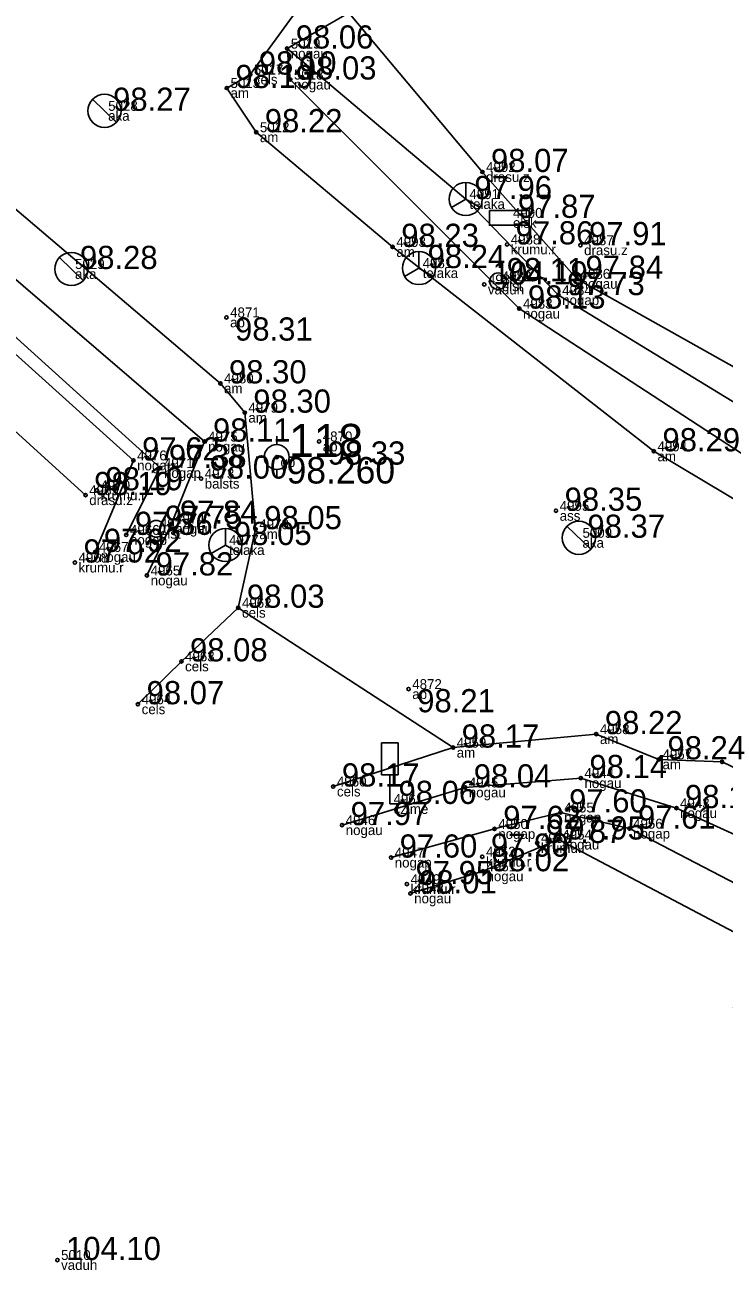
# Model space of a CAD drawing. Extents: x 614911 to 615803, y 262110 to 264311.
# Drawn here: x 615316.57 to 615337.66, y 264059.95 to 264097.55 of the extents above; entities that cross this region are included whole.
import ezdxf

# ---------------------------------------------------------------- set-up
doc = ezdxf.new("R2010")
doc.units = 0
for name, color, linetype in [('Level 12', 7, 'Continuous'), ('Level 16', 7, 'Continuous'), ('Level 18', 7, 'Continuous'), ('Level 19', 7, 'Continuous'), ('Level 31', 7, 'Continuous'), ('Level 35', 7, 'Continuous'), ('Level 37', 7, 'Continuous'), ('Level 49', 7, 'Continuous'), ('Level 53', 7, 'Continuous'), ('Level 54', 7, 'Continuous'), ('Level 57', 7, 'Continuous'), ('Level 58', 7, 'Continuous')]:
    doc.layers.add(name, color=color, linetype=linetype)

msp = doc.modelspace()

# ---------------------------------------------------------------- linework, layer by layer
at = {"layer": 'Level 12'}
for p, q in [((615318.611, 264095.3), (615319.329, 264094.604)), ((615317.612, 264090.524), (615318.33, 264089.828)), ((615332.921, 264082.409), (615333.639, 264081.713))]:
    msp.add_line(p, q, dxfattribs=at)
for centre in [(615318.97, 264094.952), (615317.971, 264090.176), (615333.28, 264082.061)]:
    msp.add_circle(centre, 0.5, dxfattribs=at)
at = {"layer": 'Level 16'}
for p, q in [((615327.826, 264075.872), (615327.326, 264075.872)), ((615327.326, 264074.903), (615327.326, 264075.872)), ((615327.826, 264074.903), (615327.826, 264075.872)), ((615327.826, 264074.903), (615327.326, 264074.903)), ((615327.58, 264074.903), (615327.58, 264074.025)), ((615327.58, 264074.025), (615327.895, 264074.025))]:
    msp.add_line(p, q, dxfattribs=at)
at = {"layer": 'Level 18'}
msp.add_lwpolyline([(615330.582, 264091.945), (615331.782, 264091.945), (615331.782, 264091.495), (615330.582, 264091.495)], close=True, dxfattribs=at)
for centre in [(615330.844, 264089.808), (615320.531, 264082.335)]:
    msp.add_circle(centre, 0.25, dxfattribs=at)
at = {"layer": 'Level 19'}
for p, q in [((615324.168, 264084.875), (615324.168, 264085.125)), ((615323.543, 264084.5), (615323.793, 264084.5)), ((615324.543, 264084.5), (615324.793, 264084.5)), ((615324.168, 264083.875), (615324.168, 264084.125))]:
    msp.add_line(p, q, dxfattribs=at)
for radius in [0.375, 0.05]:
    msp.add_circle((615324.168, 264084.5), radius, dxfattribs=at)
at = {"layer": 'Level 31'}
msp.add_lwpolyline([(615342.554, 264084.637), (615342.735, 264083.235), (615341.151, 264082.675), (615331.485, 264088.981), (615324.574, 264095.897), (615324.48, 264096.832), (615326.347, 264097.906), (615330.371, 264093.105), (615333.223, 264089.88)], close=True, dxfattribs=at)
for points in [[(615342.735, 264083.235), (615332.667, 264089.387), (615329.869, 264092.288), (615324.48, 264096.832)], [(615308.836, 264096.256), (615308.054, 264095.857), (615308.103, 264094.982), (615319.844, 264084.397), (615318.691, 264081.635)], [(615320.252, 264080.924), (615320.987, 264082.487), (615321.984, 264084.966), (615308.836, 264096.256)], [(615308.546, 264095.126), (615320.654, 264084.169), (615319.629, 264082.149)], [(615326.136, 264073.386), (615329.85, 264074.524), (615333.34, 264074.806), (615336.223, 264073.9), (615340.962, 264071.745), (615340.155, 264068.995), (615332.671, 264072.951), (615330.385, 264071.993), (615328.202, 264071.325)], [(615327.615, 264072.406), (615330.74, 264073.271), (615332.728, 264073.768), (615334.806, 264073.28), (615340.788, 264070.174)]]:
    msp.add_lwpolyline(points, dxfattribs=at)
at = {"layer": 'Level 35'}
msp.add_lwpolyline([(615295.211, 264104.76), (615304.502, 264095.994), (615318.399, 264083.349)], dxfattribs=at)
at = {"layer": 'Level 37'}
msp.add_line((615323.007, 264079.949), (615329.485, 264075.727), dxfattribs=at)
for points in [[(615251.734, 264144.277), (615251.633, 264145.05), (615254.814, 264144.913), (615255.586, 264144.369), (615256.375, 264144.483), (615257.281, 264144.058), (615263.551, 264138.488), (615263.475, 264137.458), (615265.76, 264135.377), (615266.557, 264135.576), (615277.526, 264126.006), (615285.274, 264119.013), (615285.183, 264118.067), (615287.886, 264115.573), (615288.589, 264115.79), (615289.414, 264115.354), (615303.495, 264102.882), (615322.466, 264086.723), (615323.2, 264085.839), (615323.53, 264082.321), (615323.007, 264079.949), (615321.29, 264078.33), (615319.981, 264077.036)], [(615359.89, 264070.688), (615358.538, 264070.925), (615335.543, 264084.672), (615327.664, 264090.843), (615323.547, 264094.306), (615322.661, 264095.641), (615323.366, 264096.047), (615324.826, 264098.05), (615325.375, 264098.771)], [(615325.872, 264074.552), (615329.485, 264075.727), (615333.806, 264076.134), (615335.694, 264075.372), (615337.602, 264075.295), (615340.087, 264074.101), (615341.021, 264072.72), (615341.144, 264070.948), (615341.165, 264070.319), (615340.734, 264069.476), (615340.35, 264068.844), (615339.781, 264068.714), (615338.581, 264069.191), (615337.946, 264067.863)]]:
    msp.add_lwpolyline(points, dxfattribs=at)
at = {"layer": 'Level 49'}
for p, q in [((615329.869, 264092.788), (615329.869, 264092.288)), ((615329.436, 264092.038), (615329.869, 264092.288)), ((615329.869, 264092.288), (615330.302, 264092.038)), ((615328.458, 264090.704), (615328.458, 264090.204)), ((615328.025, 264089.954), (615328.458, 264090.204)), ((615328.458, 264090.204), (615328.891, 264089.954)), ((615322.617, 264082.342), (615322.617, 264081.842)), ((615322.184, 264081.592), (615322.617, 264081.842)), ((615322.617, 264081.842), (615323.05, 264081.592))]:
    msp.add_line(p, q, dxfattribs=at)
for centre in [(615329.869, 264092.288), (615328.458, 264090.204), (615322.617, 264081.842)]:
    msp.add_circle(centre, 0.5, dxfattribs=at)
at = {"layer": 'Level 57'}
for centre in [(615324.48, 264096.832), (615323.366, 264096.047), (615324.574, 264095.897), (615322.661, 264095.641), (615323.547, 264094.306), (615330.371, 264093.105), (615327.664, 264090.843), (615331.115, 264090.919), (615333.328, 264090.895), (615333.223, 264089.88), (615330.426, 264089.709), (615332.667, 264089.387), (615331.485, 264088.981), (615322.649, 264088.715), (615322.466, 264086.723), (615323.2, 264085.839), (615325.444, 264084.971), (615321.984, 264084.966), (615335.543, 264084.672), (615319.844, 264084.397), (615320.654, 264084.169), (615321.883, 264083.847), (615318.738, 264083.495), (615318.399, 264083.349), (615332.592, 264082.876), (615320.987, 264082.487), (615319.629, 264082.149), (615323.53, 264082.321), (615318.691, 264081.635), (615318.076, 264081.314), (615320.252, 264080.924), (615323.007, 264079.949), (615321.29, 264078.33), (615328.144, 264077.493), (615319.981, 264077.036), (615333.806, 264076.134), (615329.485, 264075.727), (615335.694, 264075.372), (615337.602, 264075.295), (615325.872, 264074.552), (615329.85, 264074.524), (615333.34, 264074.806), (615332.728, 264073.768), (615336.223, 264073.9), (615326.136, 264073.386), (615330.74, 264073.271), (615332.671, 264072.951), (615334.806, 264073.28), (615332.025, 264072.848), (615327.615, 264072.406), (615330.369, 264072.433), (615330.385, 264071.993), (615328.094, 264071.604), (615328.202, 264071.325), (615317.549, 264060.256)]:
    msp.add_circle(centre, 0.05, dxfattribs=at)
at = {"layer": 'Level 58'}
for centre in [(615324.48, 264096.832), (615323.366, 264096.047), (615324.574, 264095.897), (615322.661, 264095.641), (615323.547, 264094.306), (615330.371, 264093.105), (615327.664, 264090.843), (615331.115, 264090.919), (615333.328, 264090.895), (615333.223, 264089.88), (615330.426, 264089.709), (615332.667, 264089.387), (615331.485, 264088.981), (615322.649, 264088.715), (615322.466, 264086.723), (615323.2, 264085.839), (615325.444, 264084.971), (615321.984, 264084.966), (615335.543, 264084.672), (615319.844, 264084.397), (615320.654, 264084.169), (615321.883, 264083.847), (615318.738, 264083.495), (615318.399, 264083.349), (615332.592, 264082.876), (615320.987, 264082.487), (615319.629, 264082.149), (615323.53, 264082.321), (615318.691, 264081.635), (615318.076, 264081.314), (615320.252, 264080.924), (615323.007, 264079.949), (615321.29, 264078.33), (615328.144, 264077.493), (615319.981, 264077.036), (615333.806, 264076.134), (615329.485, 264075.727), (615335.694, 264075.372), (615337.602, 264075.295), (615325.872, 264074.552), (615329.85, 264074.524), (615333.34, 264074.806), (615332.728, 264073.768), (615336.223, 264073.9), (615326.136, 264073.386), (615330.74, 264073.271), (615332.671, 264072.951), (615334.806, 264073.28), (615332.025, 264072.848), (615327.615, 264072.406), (615330.369, 264072.433), (615330.385, 264071.993), (615328.094, 264071.604), (615328.202, 264071.325), (615317.549, 264060.256)]:
    msp.add_circle(centre, 0.05, dxfattribs=at)

# ---------------------------------------------------------------- texts
at = {"layer": 'Level 19'}
for s, height, p in [(' 118', 1, (615324.168, 264084.5)), (' 98.260', 0.8, (615324.168, 264083.7))]:
    msp.add_text(s, height=height, dxfattribs=at).set_placement(p)
at = {"layer": 'Level 49'}
for s, p in [(' 97.96', (615329.869, 264092.288)), (' 98.24', (615328.458, 264090.204)), (' 98.05', (615322.617, 264081.842))]:
    msp.add_text(s, height=0.7, dxfattribs=at).set_placement(p)
at = {"layer": 'Level 53'}
for s, p in [(' nogau', (615324.48, 264096.532)), (' cels', (615323.366, 264095.747)), (' am', (615322.661, 264095.341)), (' nogau', (615324.574, 264095.597)), (' aka', (615318.97, 264094.652)), (' am', (615323.547, 264094.006)), (' drasu.z', (615330.371, 264092.805)), (' telaka', (615329.869, 264091.988)), (' elsk', (615331.182, 264091.42)), (' am', (615327.664, 264090.543)), (' krumu.r', (615331.115, 264090.619)), (' drasu.z', (615333.328, 264090.595)), (' aka', (615317.971, 264089.876)), (' telaka', (615328.458, 264089.904)), (' vaduh', (615330.426, 264089.409)), (' elst', (615330.844, 264089.508)), (' nogau', (615333.223, 264089.58)), (' nogap', (615332.667, 264089.087)), (' nogau', (615331.485, 264088.681)), (' ap', (615322.649, 264088.415)), (' am', (615322.466, 264086.423)), (' am', (615323.2, 264085.539)), (' nogau', (615321.984, 264084.666)), (' ap', (615325.444, 264084.671)), (' nogau', (615319.844, 264084.097)), (' gp', (615324.168, 264084.2)), (' am', (615335.543, 264084.372)), (' nogap', (615320.654, 264083.869)), (' balsts', (615321.883, 264083.547)), (' drasu.z', (615318.399, 264083.049)), (' krumu.r', (615318.738, 264083.195)), (' ass', (615332.592, 264082.576)), (' nogau', (615320.987, 264082.187)), (' nogap', (615319.629, 264081.849)), (' elst', (615320.531, 264082.035)), (' am', (615323.53, 264082.021)), (' aka', (615333.28, 264081.761)), (' telaka', (615322.617, 264081.542)), (' krumu.r', (615318.076, 264081.014)), (' nogau', (615318.691, 264081.335)), (' nogau', (615320.252, 264080.624)), (' cels', (615323.007, 264079.649)), (' cels', (615321.29, 264078.03)), (' ap', (615328.144, 264077.193)), (' cels', (615319.981, 264076.736)), (' am', (615333.806, 264075.834)), (' am', (615329.485, 264075.427)), (' am', (615335.694, 264075.072)), (' cels', (615325.872, 264074.252)), (' nogau', (615333.34, 264074.506)), (' nogau', (615329.85, 264074.224)), (' czime', (615327.58, 264073.725)), (' nogau', (615336.223, 264073.6)), (' nogap', (615332.728, 264073.468)), (' nogau', (615326.136, 264073.086)), (' nogap', (615330.74, 264072.971)), (' nogap', (615334.806, 264072.98)), (' krumu.r', (615332.025, 264072.548)), (' nogau', (615332.671, 264072.651)), (' nogap', (615327.615, 264072.106)), (' krumu.r', (615330.369, 264072.133)), (' nogau', (615330.385, 264071.693)), (' krumu.r', (615328.094, 264071.304)), (' nogau', (615328.202, 264071.025)), (' vaduh', (615317.549, 264059.956))]:
    msp.add_text(s, height=0.3, dxfattribs=at).set_placement(p)
at = {"layer": 'Level 54'}
for s, p in [(' 5019', (615324.48, 264096.832)), (' 5017', (615323.366, 264096.047)), (' 5013', (615322.661, 264095.641)), (' 5018', (615324.574, 264095.897)), (' 5028', (615318.97, 264094.952)), (' 5012', (615323.547, 264094.306)), (' 4992', (615330.371, 264093.105)), (' 4991', (615329.869, 264092.288)), (' 4990', (615331.182, 264091.72)), (' 4993', (615327.664, 264090.843)), (' 4988', (615331.115, 264090.919)), (' 4987', (615333.328, 264090.895)), (' 5029', (615317.971, 264090.176)), (' 4981', (615328.458, 264090.204)), (' 4985', (615330.426, 264089.709)), (' 4982', (615330.844, 264089.808)), (' 4986', (615333.223, 264089.88)), (' 4984', (615332.667, 264089.387)), (' 4983', (615331.485, 264088.981)), (' 4871', (615322.649, 264088.715)), (' 4980', (615322.466, 264086.723)), (' 4979', (615323.2, 264085.839)), (' 4975', (615321.984, 264084.966)), (' 4870', (615325.444, 264084.971)), (' 4976', (615319.844, 264084.397)), (' 4994', (615335.543, 264084.672)), (' 4971', (615320.654, 264084.169)), (' 4973', (615321.883, 264083.847)), (' 4969', (615318.399, 264083.349)), (' 4970', (615318.738, 264083.495)), (' 4995', (615332.592, 264082.876)), (' 4974', (615320.987, 264082.487)), (' 4966', (615319.629, 264082.149)), (' 4972', (615320.531, 264082.335)), (' 4978', (615323.53, 264082.321)), (' 4977', (615322.617, 264081.842)), (' 5009', (615333.28, 264082.061)), (' 4967', (615318.691, 264081.635)), (' 4968', (615318.076, 264081.314)), (' 4965', (615320.252, 264080.924)), (' 4962', (615323.007, 264079.949)), (' 4963', (615321.29, 264078.33)), (' 4872', (615328.144, 264077.493)), (' 4964', (615319.981, 264077.036)), (' 4958', (615333.806, 264076.134)), (' 4959', (615329.485, 264075.727)), (' 4957', (615335.694, 264075.372)), (' 4944', (615333.34, 264074.806)), (' 4960', (615325.872, 264074.552)), (' 4945', (615329.85, 264074.524)), (' 4961', (615327.58, 264074.025)), (' 4943', (615336.223, 264073.9)), (' 4955', (615332.728, 264073.768)), (' 4946', (615326.136, 264073.386)), (' 4950', (615330.74, 264073.271)), (' 4956', (615334.806, 264073.28)), (' 4953', (615332.025, 264072.848)), (' 4954', (615332.671, 264072.951)), (' 4947', (615327.615, 264072.406)), (' 4952', (615330.369, 264072.433)), (' 4951', (615330.385, 264071.993)), (' 4949', (615328.094, 264071.604)), (' 4948', (615328.202, 264071.325)), (' 5010', (615317.549, 264060.256))]:
    msp.add_text(s, height=0.3, dxfattribs=at).set_placement(p)
at = {"layer": 'Level 58'}
for s, p in [(' 98.06', (615324.48, 264096.832)), (' 98.10', (615323.366, 264096.047)), (' 98.19', (615322.661, 264095.641)), (' 98.03', (615324.574, 264095.897)), (' 98.27', (615318.97, 264094.952)), (' 98.22', (615323.547, 264094.306)), (' 98.07', (615330.371, 264093.105)), (' 97.87', (615331.182, 264091.72)), (' 98.23', (615327.664, 264090.843)), (' 97.86', (615331.115, 264090.919)), (' 97.91', (615333.328, 264090.895)), (' 98.28', (615317.971, 264090.176)), (' 104.19', (615330.426, 264089.709)), (' 98.11', (615330.844, 264089.808)), (' 97.84', (615333.223, 264089.88)), (' 97.73', (615332.667, 264089.387)), (' 98.13', (615331.485, 264088.981)), (' 98.31', (615322.649, 264088.015)), (' 98.30', (615322.466, 264086.723)), (' 98.30', (615323.2, 264085.839)), (' 98.11', (615321.984, 264084.966)), (' 97.62', (615319.844, 264084.397)), (' 98.29', (615335.543, 264084.672)), (' 97.38', (615320.654, 264084.169)), (' 98.33', (615325.444, 264084.271)), (' 98.00', (615321.883, 264083.847)), (' 98.19', (615318.399, 264083.349)), (' 98.19', (615318.738, 264083.495)), (' 98.35', (615332.592, 264082.876)), (' 97.84', (615320.987, 264082.487)), (' 97.36', (615319.629, 264082.149)), (' 97.75', (615320.531, 264082.335)), (' 98.05', (615323.53, 264082.321)), (' 98.37', (615333.28, 264082.061)), (' 97.92', (615318.076, 264081.314)), (' 97.92', (615318.691, 264081.635)), (' 97.82', (615320.252, 264080.924)), (' 98.03', (615323.007, 264079.949)), (' 98.08', (615321.29, 264078.33)), (' 98.07', (615319.981, 264077.036)), (' 98.21', (615328.144, 264076.793)), (' 98.22', (615333.806, 264076.134)), (' 98.17', (615329.485, 264075.727)), (' 98.24', (615335.694, 264075.372)), (' 98.17', (615325.872, 264074.552)), (' 98.14', (615333.34, 264074.806)), (' 98.04', (615329.85, 264074.524)), (' 98.06', (615327.58, 264074.025)), (' 98.18', (615336.223, 264073.9)), (' 97.60', (615332.728, 264073.768)), (' 97.97', (615326.136, 264073.386)), (' 97.62', (615330.74, 264073.271)), (' 97.61', (615334.806, 264073.28)), (' 97.87', (615332.025, 264072.848)), (' 97.95', (615332.671, 264072.951)), (' 97.60', (615327.615, 264072.406)), (' 97.90', (615330.369, 264072.433)), (' 98.02', (615330.385, 264071.993)), (' 97.95', (615328.094, 264071.604)), (' 98.01', (615328.202, 264071.325)), (' 104.10', (615317.549, 264060.256))]:
    msp.add_text(s, height=0.7, dxfattribs=at).set_placement(p)

doc.saveas('drawing.dxf')
